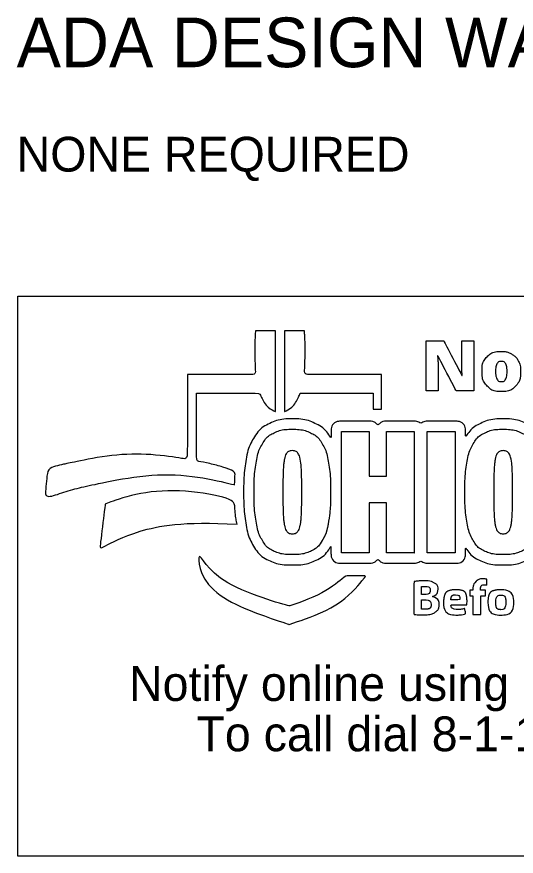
# Model space of a CAD drawing. Extents: x 0 to 34, y 0 to 22.
# Drawn here: x 1.995 to 4.005, y 2.15 to 5.529 of the extents above; entities that cross this region are included whole.
import ezdxf

# ---------------------------------------------------------------- set-up
doc = ezdxf.new("R2010")
doc.units = 0
for name, color, linetype in [('GM_X_State_Route', 7, 'Continuous'), ('SH_Data', 7, 'Continuous'), ('SH_Text', 7, 'Continuous')]:
    doc.layers.add(name, color=color, linetype=linetype)

msp = doc.modelspace()

# ---------------------------------------------------------------- linework, layer by layer
at = {"layer": 'GM_X_State_Route'}
for points, degree in [([(2.8714, 3.6451), (2.8714, 3.6451), (2.8713, 3.6451), (2.8713, 3.6451), (2.7035, 3.6848), (2.5151, 3.6887), (2.3198, 3.6488), (2.2463, 3.6337), (2.1755, 3.613), (2.1076, 3.5876), (2.1114, 3.6278), (2.1154, 3.6704), (2.1192, 3.7105), (2.1512, 3.7194), (2.1834, 3.7277), (2.2164, 3.7345), (2.3789, 3.7677), (2.5364, 3.7705), (2.6813, 3.7475), (2.6813, 3.7475), (2.6813, 4.0883), (2.6813, 4.0883), (2.6813, 4.0883), (2.9557, 4.0883), (2.9557, 4.0883), (2.9507, 4.1972), (2.9557, 4.2641), (2.9557, 4.2641), (2.9557, 4.2641), (3.0355, 4.2641), (3.0355, 4.2641), (3.0355, 4.2641), (3.0355, 3.9394), (3.0355, 3.9394), (3.0355, 3.9394), (2.9956, 3.96), (2.9721, 4.0141), (2.9721, 4.0141), (2.7181, 4.0141), (2.7181, 4.0141), (2.7181, 4.0141), (2.7181, 3.741), (2.7181, 3.741), (2.7723, 3.7307), (2.8247, 3.7167), (2.8747, 3.6992), (2.873, 3.6825), (2.872, 3.6646), (2.8714, 3.6451)], 3), ([(3.1358, 4.0142), (3.1358, 4.0142), (3.1359, 4.0142), (3.1359, 4.0142), (3.1125, 3.9602), (3.0726, 3.9395), (3.0726, 3.9395), (3.0726, 3.9395), (3.0726, 4.2641), (3.0726, 4.2641), (3.0726, 4.2641), (3.1523, 4.2641), (3.1523, 4.2641), (3.1523, 4.2641), (3.1573, 4.1972), (3.1523, 4.0883), (3.1523, 4.0883), (3.4633, 4.0883), (3.4633, 4.0883), (3.4633, 4.0883), (3.4633, 3.9487), (3.4633, 3.9487), (3.4633, 3.9487), (3.4285, 3.9487), (3.4285, 3.9487), (3.4285, 3.9487), (3.4285, 4.0142), (3.4285, 4.0142), (3.4285, 4.0142), (3.1358, 4.0142), (3.1358, 4.0142)], 3), ([(3.8339, 4.0232), (3.8339, 4.0232), (3.8339, 4.2238), (3.8339, 4.2238), (3.8339, 4.2238), (3.7856, 4.2238), (3.7856, 4.2238), (3.7856, 4.2238), (3.7856, 4.1331), (3.7856, 4.1331), (3.7856, 4.1208), (3.7862, 4.1046), (3.7875, 4.0844), (3.7875, 4.0844), (3.7867, 4.0844), (3.7867, 4.0844), (3.7867, 4.0844), (3.7137, 4.2238), (3.7137, 4.2238), (3.7137, 4.2238), (3.6429, 4.2238), (3.6429, 4.2238), (3.6429, 4.2238), (3.6429, 4.0232), (3.6429, 4.0232), (3.6429, 4.0232), (3.6909, 4.0232), (3.6909, 4.0232), (3.6909, 4.0232), (3.6909, 4.1136), (3.6909, 4.1136), (3.6909, 4.1253), (3.69, 4.1423), (3.6883, 4.1645), (3.6883, 4.1645), (3.6895, 4.1645), (3.6895, 4.1645), (3.6895, 4.1645), (3.7628, 4.0232), (3.7628, 4.0232), (3.7628, 4.0232), (3.8339, 4.0232), (3.8339, 4.0232)], 3), ([(4.0224, 4.1013), (4.0224, 4.1175), (4.0193, 4.1316), (4.0129, 4.1437), (4.0066, 4.1558), (3.9975, 4.1651), (3.9858, 4.1716), (3.9741, 4.1781), (3.9606, 4.1814), (3.9454, 4.1814), (3.9206, 4.1814), (3.9015, 4.1743), (3.8878, 4.1603), (3.8741, 4.1463), (3.8673, 4.1266), (3.8673, 4.1013), (3.8673, 4.0765), (3.8743, 4.0568), (3.8882, 4.0423), (3.9022, 4.0277), (3.9209, 4.0205), (3.9445, 4.0205), (3.9691, 4.0205), (3.9882, 4.0276), (4.0019, 4.0418), (4.0156, 4.056), (4.0224, 4.0758), (4.0224, 4.1013)], 3), ([(3.9217, 4.1013), (3.9217, 4.1146), (3.9235, 4.1246), (3.9271, 4.1313), (3.9306, 4.1381), (3.9366, 4.1414), (3.9448, 4.1414), (3.9532, 4.1414), (3.9591, 4.1381), (3.9626, 4.1313), (3.9661, 4.1245), (3.9679, 4.1145), (3.9679, 4.1013), (3.9679, 4.0879), (3.9661, 4.0778), (3.9627, 4.0708), (3.9593, 4.0638), (3.9534, 4.0603), (3.9451, 4.0603), (3.9366, 4.0603), (3.9306, 4.0638), (3.9271, 4.0708), (3.9235, 4.0778), (3.9217, 4.0879), (3.9217, 4.1013)], 3), ([(4.453, 3.8646), (4.4213, 3.8951), (4.3771, 3.9098), (4.318, 3.9098), (4.2071, 3.9098), (4.1436, 3.854), (4.1375, 3.7525), (4.1311, 3.7837), (4.1218, 3.8097), (4.1088, 3.8314), (4.0924, 3.8589), (4.0703, 3.8793), (4.043, 3.8922), (4.0177, 3.9042), (3.9873, 3.9103), (3.9525, 3.9103), (3.9177, 3.9103), (3.8873, 3.9042), (3.8621, 3.8922), (3.8373, 3.8805), (3.8171, 3.8623), (3.8012, 3.8386), (3.8012, 3.8386), (3.8012, 3.8587), (3.8012, 3.8587), (3.8012, 3.8819), (3.7824, 3.9007), (3.7592, 3.9007), (3.7592, 3.9007), (3.6469, 3.9007), (3.6469, 3.9007), (3.637, 3.9007), (3.6282, 3.8967), (3.6209, 3.8909), (3.6137, 3.8967), (3.6049, 3.9007), (3.5949, 3.9007), (3.5949, 3.9007), (3.4826, 3.9007), (3.4826, 3.9007), (3.4684, 3.9007), (3.4559, 3.8937), (3.4482, 3.8828), (3.4406, 3.8937), (3.4281, 3.9007), (3.4138, 3.9007), (3.4138, 3.9007), (3.3016, 3.9007), (3.3016, 3.9007), (3.2784, 3.9007), (3.2595, 3.882), (3.2595, 3.8587), (3.2595, 3.8587), (3.2595, 3.8325), (3.2595, 3.8325), (3.2432, 3.8594), (3.2214, 3.8795), (3.1945, 3.8922), (3.1692, 3.9042), (3.1388, 3.9103), (3.104, 3.9103), (3.0692, 3.9103), (3.0388, 3.9042), (3.0136, 3.8922), (2.9862, 3.8793), (2.9641, 3.8589), (2.9477, 3.8314), (2.9329, 3.8067), (2.9224, 3.7753), (2.9163, 3.7382), (2.9108, 3.704), (2.9079, 3.6626), (2.9079, 3.6152), (2.9079, 3.5678), (2.9108, 3.5263), (2.9163, 3.4921), (2.9224, 3.455), (2.9329, 3.4236), (2.9477, 3.3989), (2.9643, 3.3711), (2.9869, 3.3507), (3.0145, 3.3386), (3.0395, 3.3277), (3.0696, 3.3221), (3.1039, 3.3221), (3.1382, 3.3221), (3.1683, 3.3277), (3.1932, 3.3386), (3.2206, 3.3506), (3.2428, 3.3706), (3.2594, 3.3978), (3.2594, 3.3978), (3.2594, 3.3716), (3.2594, 3.3716), (3.2594, 3.3485), (3.2783, 3.3296), (3.3015, 3.3296), (3.3015, 3.3296), (3.4138, 3.3296), (3.4138, 3.3296), (3.428, 3.3296), (3.4405, 3.3367), (3.4481, 3.3475), (3.4558, 3.3367), (3.4683, 3.3296), (3.4825, 3.3296), (3.4825, 3.3296), (3.5948, 3.3296), (3.5948, 3.3296), (3.6048, 3.3296), (3.6136, 3.3336), (3.6208, 3.3394), (3.6281, 3.3336), (3.6369, 3.3296), (3.6468, 3.3296), (3.6468, 3.3296), (3.7591, 3.3296), (3.7591, 3.3296), (3.7823, 3.3296), (3.8011, 3.3484), (3.8011, 3.3716), (3.8011, 3.3716), (3.8011, 3.3918), (3.8011, 3.3918), (3.8172, 3.3677), (3.8379, 3.3497), (3.8631, 3.3386), (3.888, 3.3277), (3.9181, 3.3221), (3.9524, 3.3221), (3.9867, 3.3221), (4.0168, 3.3277), (4.0417, 3.3386), (4.0695, 3.3507), (4.0921, 3.3711), (4.1086, 3.3988), (4.1193, 3.4168), (4.1276, 3.4377), (4.1338, 3.462), (4.139, 3.4218), (4.154, 3.3892), (4.179, 3.3652), (4.2113, 3.3341), (4.2566, 3.3191), (4.3178, 3.3191), (4.4037, 3.3191), (4.4613, 3.352), (4.4871, 3.4125), (4.4871, 3.4125), (4.4956, 3.4125), (4.4956, 3.4125), (4.4956, 3.4125), (4.4956, 3.3651), (4.4956, 3.3651), (4.4956, 3.3427), (4.5137, 3.3245), (4.5361, 3.3245), (4.5361, 3.3245), (4.6599, 3.3245), (4.6599, 3.3245), (4.6823, 3.3245), (4.7005, 3.3427), (4.7005, 3.3651), (4.7005, 3.3651), (4.7005, 3.6372), (4.7005, 3.6372), (4.7019, 3.6372), (4.7031, 3.637), (4.7045, 3.637), (4.7045, 3.637), (4.7045, 3.3651), (4.7045, 3.3651), (4.7045, 3.3427), (4.7227, 3.3245), (4.745, 3.3245), (4.745, 3.3245), (4.8689, 3.3245), (4.8689, 3.3245), (4.8837, 3.3245), (4.8966, 3.3326), (4.9037, 3.3446), (4.9094, 3.3367), (4.9187, 3.3315), (4.9293, 3.3315), (4.9293, 3.3315), (4.9996, 3.3315), (4.9996, 3.3315), (5.0172, 3.3315), (5.0315, 3.3457), (5.0315, 3.3633), (5.0315, 3.3633), (5.0315, 3.3918), (5.0315, 3.3918), (5.0328, 3.3884), (5.0338, 3.3849), (5.0355, 3.3818), (5.045, 3.3639), (5.0591, 3.3499), (5.0777, 3.3401), (5.0954, 3.3308), (5.1174, 3.3262), (5.1449, 3.3262), (5.1725, 3.3262), (5.1943, 3.3314), (5.2119, 3.3416), (5.2292, 3.3517), (5.2426, 3.3656), (5.252, 3.3827), (5.252, 3.3827), (5.252, 3.3633), (5.252, 3.3633), (5.252, 3.3457), (5.2663, 3.3315), (5.2839, 3.3315), (5.2839, 3.3315), (5.3593, 3.3315), (5.3593, 3.3315), (5.3769, 3.3315), (5.3912, 3.3457), (5.3912, 3.3633), (5.3912, 3.3633), (5.3912, 3.503), (5.3912, 3.503), (5.3912, 3.511), (5.3923, 3.5146), (5.3921, 3.515), (5.3936, 3.5159), (5.4002, 3.517), (5.4075, 3.5163), (5.4098, 3.5161), (5.412, 3.5157), (5.4145, 3.5153), (5.416, 3.515), (5.4175, 3.5155), (5.4191, 3.5154), (5.4189, 3.5092), (5.4184, 3.5037), (5.4184, 3.4969), (5.4184, 3.4675), (5.4207, 3.4439), (5.4254, 3.4247), (5.4301, 3.4055), (5.4363, 3.3902), (5.4442, 3.3781), (5.4411, 3.3765), (5.4384, 3.3745), (5.436, 3.372), (5.43, 3.366), (5.4267, 3.3577), (5.4269, 3.3492), (5.4272, 3.33), (5.4308, 3.3134), (5.4375, 3.2999), (5.4446, 3.2856), (5.4545, 3.2741), (5.4671, 3.2655), (5.4787, 3.2578), (5.492, 3.2524), (5.5067, 3.2496), (5.5192, 3.2471), (5.5327, 3.2459), (5.5468, 3.2459), (5.5628, 3.2459), (5.5781, 3.2477), (5.5922, 3.2514), (5.6082, 3.2556), (5.6222, 3.2627), (5.6341, 3.2724), (5.6468, 3.2826), (5.6566, 3.2962), (5.6636, 3.3127), (5.6701, 3.3283), (5.6734, 3.3467), (5.6734, 3.3676), (5.6734, 3.3676), (5.6734, 3.6196), (5.6734, 3.6196), (5.6734, 3.6372), (5.6592, 3.6514), (5.6416, 3.6514), (5.6416, 3.6514), (5.6416, 3.6513), (5.6416, 3.6513)], 3), ([(3.224, 3.4204), (3.2119, 3.4002), (3.196, 3.3857), (3.1763, 3.3771), (3.1565, 3.3685), (3.1324, 3.3641), (3.1038, 3.3641), (3.0751, 3.3641), (3.051, 3.3684), (3.0314, 3.3771), (3.0116, 3.3857), (2.9958, 3.4002), (2.9837, 3.4204), (2.9715, 3.4406), (2.9629, 3.4668), (2.9577, 3.4989), (2.9524, 3.5309), (2.9499, 3.5697), (2.9499, 3.6152), (2.9499, 3.6606), (2.9525, 3.6994), (2.9577, 3.7315), (2.9629, 3.7635), (2.9715, 3.7897), (2.9837, 3.8099), (2.9958, 3.8302), (3.0116, 3.8449), (3.0314, 3.8543), (3.0511, 3.8637), (3.0752, 3.8683), (3.1038, 3.8683), (3.1323, 3.8683), (3.1565, 3.8636), (3.1763, 3.8543), (3.196, 3.845), (3.2119, 3.8302), (3.224, 3.8099), (3.2361, 3.7897), (3.2447, 3.7635), (3.25, 3.7315), (3.2551, 3.6994), (3.2578, 3.6606), (3.2578, 3.6152), (3.2578, 3.5697), (3.2551, 3.5309), (3.25, 3.4989)], 3), ([(3.4825, 3.3716), (3.4825, 3.3716), (3.4825, 3.5723), (3.4825, 3.5723), (3.4825, 3.5723), (3.4137, 3.5723), (3.4137, 3.5723), (3.4137, 3.5723), (3.4137, 3.3716), (3.4137, 3.3716), (3.4137, 3.3716), (3.3014, 3.3716), (3.3014, 3.3716), (3.3014, 3.3716), (3.3014, 3.8588), (3.3014, 3.8588), (3.3014, 3.8588), (3.4137, 3.8588), (3.4137, 3.8588), (3.4137, 3.8588), (3.4137, 3.6801), (3.4137, 3.6801), (3.4137, 3.6801), (3.4825, 3.6801), (3.4825, 3.6801), (3.4825, 3.6801), (3.4825, 3.8588), (3.4825, 3.8588), (3.4825, 3.8588), (3.5947, 3.8588), (3.5947, 3.8588), (3.5947, 3.8588), (3.5947, 3.3716), (3.5947, 3.3716)], 3), ([(3.6466, 3.3716), (3.6466, 3.3716), (3.6466, 3.8588), (3.6466, 3.8588), (3.6466, 3.8588), (3.7589, 3.8588), (3.7589, 3.8588), (3.7589, 3.8588), (3.7589, 3.3716), (3.7589, 3.3716)], 3), ([(4.0723, 3.4204), (4.0602, 3.4002), (4.0444, 3.3857), (4.0246, 3.3771), (4.0049, 3.3685), (3.9807, 3.3641), (3.9521, 3.3641), (3.9235, 3.3641), (3.8993, 3.3684), (3.8797, 3.3771), (3.86, 3.3857), (3.8441, 3.4002), (3.832, 3.4204), (3.8199, 3.4406), (3.8113, 3.4668), (3.806, 3.4989), (3.8007, 3.5309), (3.7982, 3.5697), (3.7982, 3.6152), (3.7982, 3.6606), (3.8008, 3.6994), (3.806, 3.7315), (3.8113, 3.7635), (3.8199, 3.7897), (3.832, 3.8099), (3.8441, 3.8302), (3.86, 3.8449), (3.8797, 3.8543), (3.8994, 3.8637), (3.9236, 3.8683), (3.9521, 3.8683), (3.9806, 3.8683), (4.0049, 3.8636), (4.0246, 3.8543), (4.0444, 3.845), (4.0602, 3.8302), (4.0723, 3.8099), (4.0844, 3.7897), (4.093, 3.7635), (4.0983, 3.7315), (4.1035, 3.6994), (4.1061, 3.6606), (4.1061, 3.6152), (4.1061, 3.5697), (4.1035, 3.5309), (4.0983, 3.4989)], 3), ([(3.1355, 3.7482), (3.1381, 3.7355), (3.1398, 3.7183), (3.1406, 3.6967), (3.1414, 3.6751), (3.1418, 3.6479), (3.1418, 3.6152), (3.1418, 3.5824), (3.1414, 3.5553), (3.1406, 3.5337), (3.1398, 3.5121), (3.1382, 3.4949), (3.1355, 3.4822), (3.1329, 3.4695), (3.1291, 3.4606), (3.1241, 3.4556), (3.1191, 3.4506), (3.1124, 3.4481), (3.1039, 3.4481), (3.0954, 3.4481), (3.0887, 3.4506), (3.0836, 3.4556), (3.0787, 3.4606), (3.0748, 3.4695), (3.0722, 3.4822), (3.0697, 3.4949), (3.0679, 3.5121), (3.0671, 3.5337), (3.0663, 3.5553), (3.0659, 3.5824), (3.0659, 3.6152), (3.0659, 3.6479), (3.0663, 3.6751), (3.0671, 3.6967), (3.0679, 3.7183), (3.0696, 3.7355), (3.0722, 3.7482), (3.0747, 3.7609), (3.0786, 3.7698), (3.0836, 3.7748), (3.0887, 3.7797), (3.0954, 3.7823), (3.1039, 3.7823), (3.1124, 3.7823), (3.119, 3.7797), (3.1241, 3.7748), (3.1291, 3.7698), (3.1329, 3.7609), (3.1355, 3.7482)], 3), ([(3.984, 3.7482), (3.9865, 3.7355), (3.9883, 3.7183), (3.9891, 3.6967), (3.9898, 3.6751), (3.9902, 3.6479), (3.9902, 3.6152), (3.9902, 3.5824), (3.9898, 3.5553), (3.9891, 3.5337), (3.9883, 3.5121), (3.9866, 3.4949), (3.984, 3.4822), (3.9813, 3.4695), (3.9775, 3.4606), (3.9725, 3.4556), (3.9676, 3.4506), (3.9608, 3.4481), (3.9523, 3.4481), (3.9438, 3.4481), (3.9372, 3.4506), (3.9321, 3.4556), (3.9271, 3.4606), (3.9233, 3.4695), (3.9206, 3.4822), (3.9181, 3.4949), (3.9163, 3.5121), (3.9156, 3.5337), (3.9148, 3.5553), (3.9144, 3.5824), (3.9144, 3.6152), (3.9144, 3.6479), (3.9148, 3.6751), (3.9156, 3.6967), (3.9163, 3.7183), (3.918, 3.7355), (3.9206, 3.7482), (3.9232, 3.7609), (3.927, 3.7698), (3.9321, 3.7748), (3.9372, 3.7797), (3.9438, 3.7823), (3.9523, 3.7823), (3.9608, 3.7823), (3.9675, 3.7797), (3.9725, 3.7748), (3.9775, 3.7698), (3.9813, 3.7609), (3.984, 3.7482)], 3), ([(2.8813, 3.4864), (2.6621, 3.4989), (2.4642, 3.4602), (2.3287, 3.387), (2.3287, 3.387), (2.3506, 3.5655), (2.3506, 3.5655), (2.3506, 3.5655), (2.3506, 3.5676), (2.3506, 3.5676), (2.4859, 3.6161), (2.6712, 3.6267), (2.8713, 3.5905), (2.8722, 3.5556), (2.8745, 3.5249), (2.8788, 3.4988), (2.8795, 3.4945), (2.8804, 3.4905), (2.8813, 3.4864)], 3), ([(3.25, 3.4989), (3.2447, 3.4668), (3.2361, 3.4406), (3.224, 3.4204)], 2), ([(3.0913, 3.1573), (3.0913, 3.1573), (3.2205, 3.197), (3.319, 3.2789), (3.319, 3.2789), (3.4016, 3.2789), (3.4016, 3.2789), (3.2958, 3.1523), (3.0911, 3.0827), (3.0911, 3.0827), (3.0911, 3.0827), (2.729, 3.2059), (2.7188, 3.4226), (2.7751, 3.2403), (3.0913, 3.1573), (3.0913, 3.1573)], 3), ([(3.5947, 3.3716), (3.5947, 3.3716), (3.4825, 3.3716), (3.4825, 3.3716)], 2), ([(3.7589, 3.3716), (3.7589, 3.3716), (3.6466, 3.3716), (3.6466, 3.3716)], 2), ([(3.6676, 3.1955), (3.6831, 3.2011), (3.6902, 3.2123), (3.6902, 3.2243), (3.6902, 3.2363), (3.6833, 3.2456), (3.6738, 3.2506), (3.6638, 3.2563), (3.6522, 3.2582), (3.6333, 3.2582), (3.6179, 3.2582), (3.6014, 3.257), (3.5933, 3.2553), (3.5933, 3.2553), (3.5933, 3.1234), (3.5933, 3.1234), (3.6002, 3.1224), (3.6115, 3.1215), (3.6268, 3.1215), (3.6541, 3.1215), (3.6708, 3.1259), (3.6807, 3.1336), (3.6892, 3.1403), (3.6949, 3.1499), (3.6949, 3.1621), (3.6949, 3.1795), (3.6833, 3.191), (3.6676, 3.1952)], 3), ([(3.8433, 3.2567), (3.8433, 3.2567), (3.8433, 3.2567), (3.8433, 3.2567), (3.8511, 3.2638), (3.8618, 3.2665), (3.8708, 3.2665), (3.8777, 3.2665), (3.883, 3.2657), (3.8873, 3.2645), (3.8873, 3.2645), (3.8861, 3.2412), (3.8861, 3.2412), (3.8834, 3.242), (3.8802, 3.2425), (3.8761, 3.2425), (3.8659, 3.2425), (3.8616, 3.2348), (3.8616, 3.2252), (3.8616, 3.2252), (3.8616, 3.2203), (3.8616, 3.2203), (3.8616, 3.2203), (3.8816, 3.2203), (3.8816, 3.2203), (3.8816, 3.2203), (3.8816, 3.198), (3.8816, 3.198), (3.8816, 3.198), (3.8618, 3.198), (3.8618, 3.198), (3.8618, 3.198), (3.8618, 3.1228), (3.8618, 3.1228), (3.8618, 3.1228), (3.8307, 3.1228), (3.8307, 3.1228), (3.8307, 3.1228), (3.8307, 3.198), (3.8307, 3.198), (3.8307, 3.198), (3.8177, 3.198), (3.8177, 3.198), (3.8177, 3.198), (3.8177, 3.2203), (3.8177, 3.2203), (3.8177, 3.2203), (3.8307, 3.2203), (3.8307, 3.2203), (3.8307, 3.2203), (3.8307, 3.2241), (3.8307, 3.2241), (3.8307, 3.2358), (3.8344, 3.2487), (3.8433, 3.2567)], 3), ([(3.6371, 3.236), (3.6511, 3.236), (3.6591, 3.2306), (3.6591, 3.2205), (3.6591, 3.2103), (3.6503, 3.2039), (3.6341, 3.2039), (3.6341, 3.2039), (3.624, 3.2039), (3.624, 3.2039), (3.624, 3.2039), (3.624, 3.2352), (3.624, 3.2352), (3.624, 3.2352), (3.624, 3.2352), (3.624, 3.2352)], 3), ([(3.624, 3.2352), (3.6266, 3.2356), (3.6304, 3.236), (3.6371, 3.236)], 2), ([(3.7626, 3.2224), (3.728, 3.2224), (3.7124, 3.1951), (3.7124, 3.1704)], 2), ([(3.7626, 3.2224), (3.7626, 3.2224), (3.7625, 3.2224), (3.7625, 3.2224)], 2), ([(3.7625, 3.2224), (3.7625, 3.2224), (3.7626, 3.2224), (3.7626, 3.2224)], 2), ([(3.7626, 3.2224), (3.7626, 3.2224), (3.7626, 3.2224), (3.7626, 3.2224)], 2), ([(3.8069, 3.1737), (3.8069, 3.1979), (3.7947, 3.2224), (3.7626, 3.2224)], 2), ([(3.8908, 3.1708), (3.8908, 3.1393), (3.9132, 3.1206), (3.9422, 3.1206), (3.9689, 3.1206), (3.9947, 3.1369), (3.9947, 3.1726), (3.9947, 3.2019), (3.9744, 3.2224), (3.9439, 3.2224)], 3), ([(3.9439, 3.2224), (3.9119, 3.2224), (3.8908, 3.2023), (3.8908, 3.1708)], 2), ([(3.624, 3.1443), (3.624, 3.1443), (3.624, 3.1822), (3.624, 3.1822), (3.624, 3.1822), (3.6345, 3.1822), (3.6345, 3.1822), (3.6499, 3.1822), (3.6624, 3.1769), (3.6624, 3.1633)], 3), ([(3.6676, 3.1952), (3.6676, 3.1954), (3.6676, 3.1955), (3.6676, 3.1955)], 2), ([(3.7609, 3.2023), (3.7751, 3.2023), (3.7784, 3.19), (3.7784, 3.1825), (3.7784, 3.1825), (3.7417, 3.1825), (3.7417, 3.1825)], 3), ([(3.7417, 3.1825), (3.7425, 3.1908), (3.7478, 3.2023), (3.7609, 3.2023)], 2), ([(3.9228, 3.1716), (3.9228, 3.186), (3.9283, 3.2009), (3.9431, 3.2009), (3.9571, 3.2009), (3.9629, 3.1862), (3.9629, 3.1716), (3.9629, 3.154), (3.9551, 3.1423), (3.9431, 3.1423)], 3), ([(3.636, 3.1439), (3.6307, 3.1439), (3.6271, 3.1439), (3.624, 3.1443)], 2), ([(3.6624, 3.1633), (3.6624, 3.1497), (3.65, 3.144), (3.636, 3.1439)], 2), ([(3.7124, 3.1704), (3.7124, 3.1399), (3.7317, 3.1208), (3.7655, 3.1208), (3.7788, 3.1208), (3.7913, 3.1227), (3.8014, 3.1267), (3.8014, 3.1267), (3.7973, 3.1473), (3.7973, 3.1473), (3.789, 3.1446), (3.7804, 3.1433), (3.7699, 3.1433), (3.7554, 3.1433), (3.7428, 3.1492), (3.7418, 3.1618), (3.7418, 3.1618), (3.8059, 3.1618), (3.8059, 3.1618), (3.8063, 3.164), (3.8069, 3.1686), (3.8069, 3.1737)], 3), ([(3.9431, 3.1423), (3.9299, 3.1423), (3.9228, 3.1548), (3.9228, 3.1716)], 2)]:
    msp.add_open_spline(points, degree=degree, dxfattribs=at)
at = {"layer": 'SH_Data'}
msp.add_lwpolyline([(1.9992, 4.4045), (6.8508, 4.4045), (6.8508, 2.15), (1.9992, 2.15)], close=True, dxfattribs=at)

# ---------------------------------------------------------------- texts
for s, p in [('Notify online using ', (2.4466, 2.775)), ('To call dial 8-1-1 or 800-362-2764', (2.718, 2.5725))]:
    msp.add_text(s, height=0.14, dxfattribs=at).set_placement(p)
at = {"layer": 'SH_Text'}
for s, height, p in [('ADA DESIGN WAIVERS', 0.2, (1.9944, 5.3256)), ('NONE REQUIRED', 0.14, (1.9944, 4.9056))]:
    msp.add_text(s, height=height, dxfattribs=at).set_placement(p)

doc.saveas('drawing.dxf')
